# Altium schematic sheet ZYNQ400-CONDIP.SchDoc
size A3
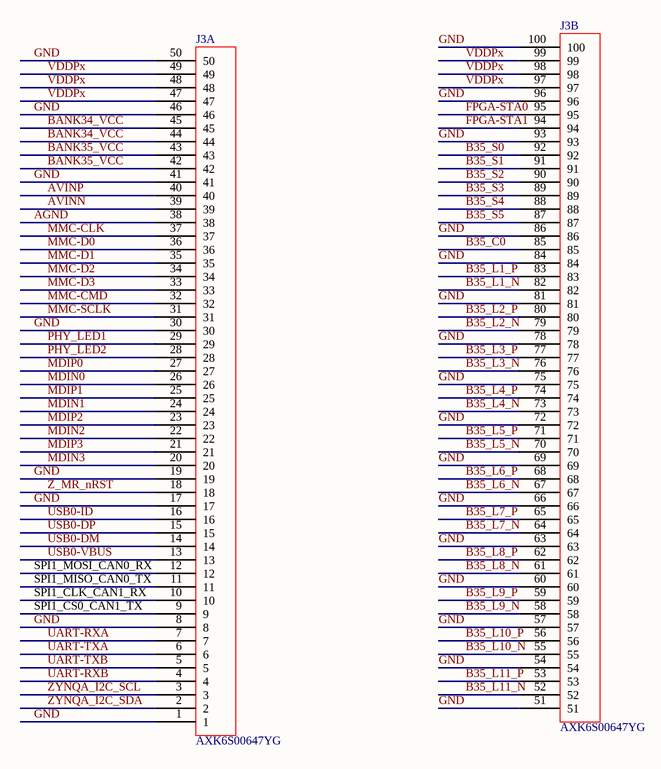
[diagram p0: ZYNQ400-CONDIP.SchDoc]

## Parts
J3  AXK6S00647YG  [AXK6S00647YG]  (parts A,B of 2)

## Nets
AGND: J3.38
AVINN: J3.39
AVINP: J3.40
B35_C0: J3.85
B35_L1_N: J3.82
B35_L1_P: J3.83
B35_L2_N: J3.79
B35_L2_P: J3.80
B35_L3_N: J3.76
B35_L3_P: J3.77
B35_L4_N: J3.73
B35_L4_P: J3.74
B35_L5_N: J3.70
B35_L5_P: J3.71
B35_L6_N: J3.67
B35_L6_P: J3.68
B35_L7_N: J3.64
B35_L7_P: J3.65
B35_L8_N: J3.61
B35_L8_P: J3.62
B35_L9_N: J3.58
B35_L9_P: J3.59
B35_L10_N: J3.55
B35_L10_P: J3.56
B35_L11_N: J3.52
B35_L11_P: J3.53
B35_S0: J3.92
B35_S1: J3.91
B35_S2: J3.90
B35_S3: J3.89
B35_S4: J3.88
B35_S5: J3.87
BANK34_VCC: J3.44 J3.45
BANK35_VCC: J3.42 J3.43
FPGA-STA0: J3.95
FPGA-STA1: J3.94
GND: J3.1 J3.8 J3.17 J3.19 J3.30 J3.41 J3.46 J3.50 J3.51 J3.54 J3.57 J3.60 J3.63 J3.66 J3.69 J3.72 J3.75 J3.78 J3.81 J3.84 J3.86 J3.93 J3.96 J3.100
MDIN0: J3.26
MDIN1: J3.24
MDIN2: J3.22
MDIN3: J3.20
MDIP0: J3.27
MDIP1: J3.25
MDIP2: J3.23
MDIP3: J3.21
MMC-CLK: J3.37
MMC-CMD: J3.32
MMC-D0: J3.36
MMC-D1: J3.35
MMC-D2: J3.34
MMC-D3: J3.33
MMC-SCLK: J3.31
PHY_LED1: J3.29
PHY_LED2: J3.28
SPI1_CLK_CAN1_RX: J3.10
SPI1_CS0_CAN1_TX: J3.9
SPI1_MISO_CAN0_TX: J3.11
SPI1_MOSI_CAN0_RX: J3.12
UART-RXA: J3.7
UART-RXB: J3.4
UART-TXA: J3.6
UART-TXB: J3.5
USB0-DM: J3.14
USB0-DP: J3.15
USB0-ID: J3.16
USB0-VBUS: J3.13
VDDPx: J3.47 J3.48 J3.49 J3.97 J3.98 J3.99
Z_MR_nRST: J3.18
ZYNQA_I2C_SCL: J3.3
ZYNQA_I2C_SDA: J3.2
